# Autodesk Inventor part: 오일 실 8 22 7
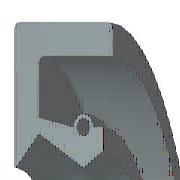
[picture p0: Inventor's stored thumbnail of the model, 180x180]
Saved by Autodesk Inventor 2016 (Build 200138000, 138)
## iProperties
IsCustomPart: 1
Created: 2012-02
Part Number: 오일 실 8 22 7
Material: 고무
Description: 오일-실
Document SubType Name: Modeling
Standard: KS B 2804
Designer: mduedu
Standards Organization: KS
Language: ko-KR
Size Designation: D - 8 22 7
Categories: <MemberInstance><Categories><Category DisplayName="샤프트 부품" InternalName="7f7aeb1f-a693-4053-b835-cee3144e0d98" Mnemonic="SHFT"><Category DisplayName="실링" Intern
Density: 0.93 g/cm^3
Appearance: 고무 - 검은색 - 버전 1.1
Author: mduedu
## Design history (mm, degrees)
revolve "본체" stored, may be unused: angle "d17" = 90 deg
revolve "스프링1" stored, may be unused: angle "d18" = 90 deg
body "Solid1"
sketch "스케치1"
  geometry: L1 (0, 11)-(7, 11); L2 (7, 9.25)-(1.75, 9.25); L3 (1.75, 5.75)-(4.9, 4); L4 (4.9, 4)-(0, 4); L5 (0, 0)-(9.586, 0) reference; L6 (4.9, 4)-(6.3, 4.875); L7 (0, 18)-(0, -3) reference; L8 (-1.941, 0)-(11.507, 0) reference; L9 (4.2, 6.1)-(1.75, 6.59); L10 (1.75, 6.59)-(1.75, 9.25); L11 (0, 11)-(0, 4.088); L12 (4.9, 4)-(0, 4); L13 (1.75, 5.75)-(0.152, 4.028); L14 (7, 11)-(7, 9.25); L15 (5.6, 6.1)-(6.3, 6.1); L16 (6.3, 6.1)-(6.3, 4.875); C1 r 0.455 at (4.9, 6.1); A1 r 0.7 centre (4.9, 6.1) between (5.6, 6.1) and (4.2, 6.1); A2 r 0.088 centre (0.088, 4.088) between (0, 4.088) and (0.152, 4.028); 1 further point
  constraints: 28 end point, 5 horizontal alignment, 5 point on line, 4 point on circle, 4 vertical alignment, 3 centre point, 3 tangent, 2 collinear, 2 horizontal, 2 perpendicular, 1 coincident, 1 parallel
  dimensions: "d0" = 22 diameter of L1 L5 (= SD2); "d1" = 1.75 distance of L1.end L2.start (= SD); "d2" = 0.91 diameter of C1 (= SPDI); "d3" = 1.4 diameter of A1 (= SPDA); "d4" = 8 diameter of L3.end L5 (= NND); "d5" = 11.5 diameter of L3.start L5 (= TKDM); "d7" = 13.18 diameter of L9.end L5 (= TKDM + 0.24 x SWDT); "d8" = 1.75 distance between parallel lines of L11 L10 (= SD); "d9" = 4.9 distance from line of L11 C1.centre (= SPDST); "d10" = 12.2 diameter of C1.centre L5 (= HLDM); "d11" = 0.0875 radius of A2 (= 0.25 x LAB); "d12" = 6.3 distance between parallel lines of L11 L16 (= SDI); "d13" = 9.75 diameter of L6.end L5 (= ABDM); "d14" = 7 distance from line of L11 L1.end (= SWDT)
fillet "모깎기1" dims "d6" = 0.3 (= RR)
other parameters: "SD2" = 22 [user parameter; used in 1 equation term], "SWDT" = 7 [user parameter; used in 2 equation terms], "RR" = 0.3 [user parameter; used in 1 equation term], "SD" = 1.75 [user parameter; used in 2 equation terms], "NND" = 8 [user parameter; used in 1 equation term], "SPDA" = 1.4 [user parameter; used in 1 equation term], "SPDI" = 0.91 [user parameter; used in 1 equation term], "TKDM" = 11.5 [user parameter; used in 2 equation terms], "HLDM" = 12.2 [user parameter; used in 1 equation term], "ABDM" = 9.75 [user parameter; used in 1 equation term], "SDI" = 6.3 [user parameter; used in 1 equation term], "SPDST" = 4.9 [user parameter; used in 1 equation term], "LAB" = 0.35 [user parameter; used in 1 equation term], "d15" = 0, "d16" = 0, "d19" = 0
